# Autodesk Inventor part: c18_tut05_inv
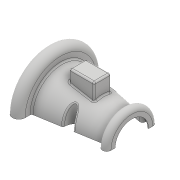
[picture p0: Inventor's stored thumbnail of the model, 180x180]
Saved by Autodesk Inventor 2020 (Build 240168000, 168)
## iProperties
Created: 2017-06
Part Number: c18_tut05_inv
Material: Generic
Document SubType Name: Modeling
Designer: CADCIM 00
Density: 1 g/cm^3
Appearance: Default
Author: CADCIM 00
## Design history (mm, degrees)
sketch "Sketch1"
  geometry: L1 (0, 30)-(0, 42.5); L2 (15, 42.5)-(15, 35); L3 (15, 35)-(90, 22.5); L4 (100, 25)-(100, 20); L5 (90, 25)-(90, 22.5); L6 (0, 0)-(90, 0); A1 r 7.5 centre (7.5, 42.5) between (15, 42.5) and (0, 42.5); A2 r 5 centre (95, 25) between (100, 25) and (90, 25)
  constraints: 12 end point, 4 point on circle, 4 tangent, 2 centre point, 2 parallel, 2 vertical, 2 vertical alignment, 1 horizontal
  dimensions: "d0" = 60 diameter of L1.start L6; "d1" = 70 diameter of L2.end L6; "d2" = 85 diameter of L1.end L6; "d3" = 100 distance between parallel lines of L4 L1; "d4" = 7.5 radius of A1; "d5" = 5 radius of A2; "d6" = 40 diameter of L4.end L6; "d7" = 45 diameter of L3.end L6; "d8" = 50 diameter of L4.start L6
feature "RevolutionSrf1" sketch "Sketch1" dims angle "d9" = 180 deg
sketch "Sketch2" dims "d10" = 5, "d11" = 10
  geometry: L1 (90, 22.5)-(15, 35) reference; 2 further points; 1 other entity
  constraints: 1 midpoint, 2 other
extrude_surface "ExtrusionSrf1" sketch "Sketch2" dims "d12" = 30, "d13" = 0
mirror "Mirror1"
feature "Trim3"
feature "Trim4"
feature "Trim5"
feature "Trim6"
workplane "Work Plane1"
sketch "Sketch3"
  geometry: L1 (35, 10)-(65, 10); L2 (65, 10)-(65, -10); L3 (65, -10)-(35, -10); L4 (35, -10)-(35, 10); 1 further point
  constraints: 8 end point, 2 parallel, 1 horizontal, 1 perpendicular
  dimensions: "d15" = 30 distance of L1.start L1.end; "d16" = 20 distance of L1.end L2.end; "d17" = 10 distance from line of point (0, 0) L3; "d18" = 35 distance from line of L4 point (0, 0)
split "Split1"
delete_face "Delete Face1"
sketch "3D Sketch1"
feature "Stitch Surface1"
fillet "Fillet1" dims "d25" = 2
thicken "Thicken1" dims "d26" = 1
body "Solid1"
body "Srf1"
body "Srf2"
body "Srf3"
node "Edges1"
body "Srf4"
body "Srf5"
body "Srf6"
extrude_surface "ExtrusionSrf2"
feature "LoftSrf1" dims "d19" = 0, "d20" = 90 deg, "d21" = 0, "d22" = 90 deg
patch "Boundary Patch1" dims "d23" = 5, "d24" = 0
other parameters: "d14" = 45
